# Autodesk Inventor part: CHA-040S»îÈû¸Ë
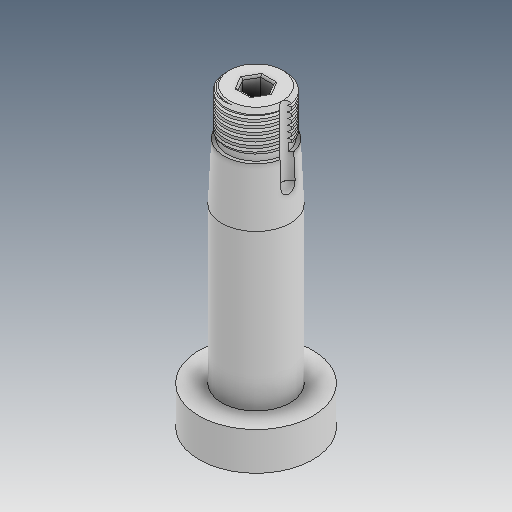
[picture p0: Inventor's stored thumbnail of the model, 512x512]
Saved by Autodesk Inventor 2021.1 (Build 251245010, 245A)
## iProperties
Created: 2019-12
Part Number: CHA-040S»îÈû¸Ë
Material: Ogólny
Document SubType Name: Modeling
Designer: user
Density: 1 g/cm^3
Appearance: Domyślna
Author: user
Revision Number: ÈÎºÎ
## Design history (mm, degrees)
feature "ÊäÈë1"
node "Bryła1"
